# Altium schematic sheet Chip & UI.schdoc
size 478 x 209 mm
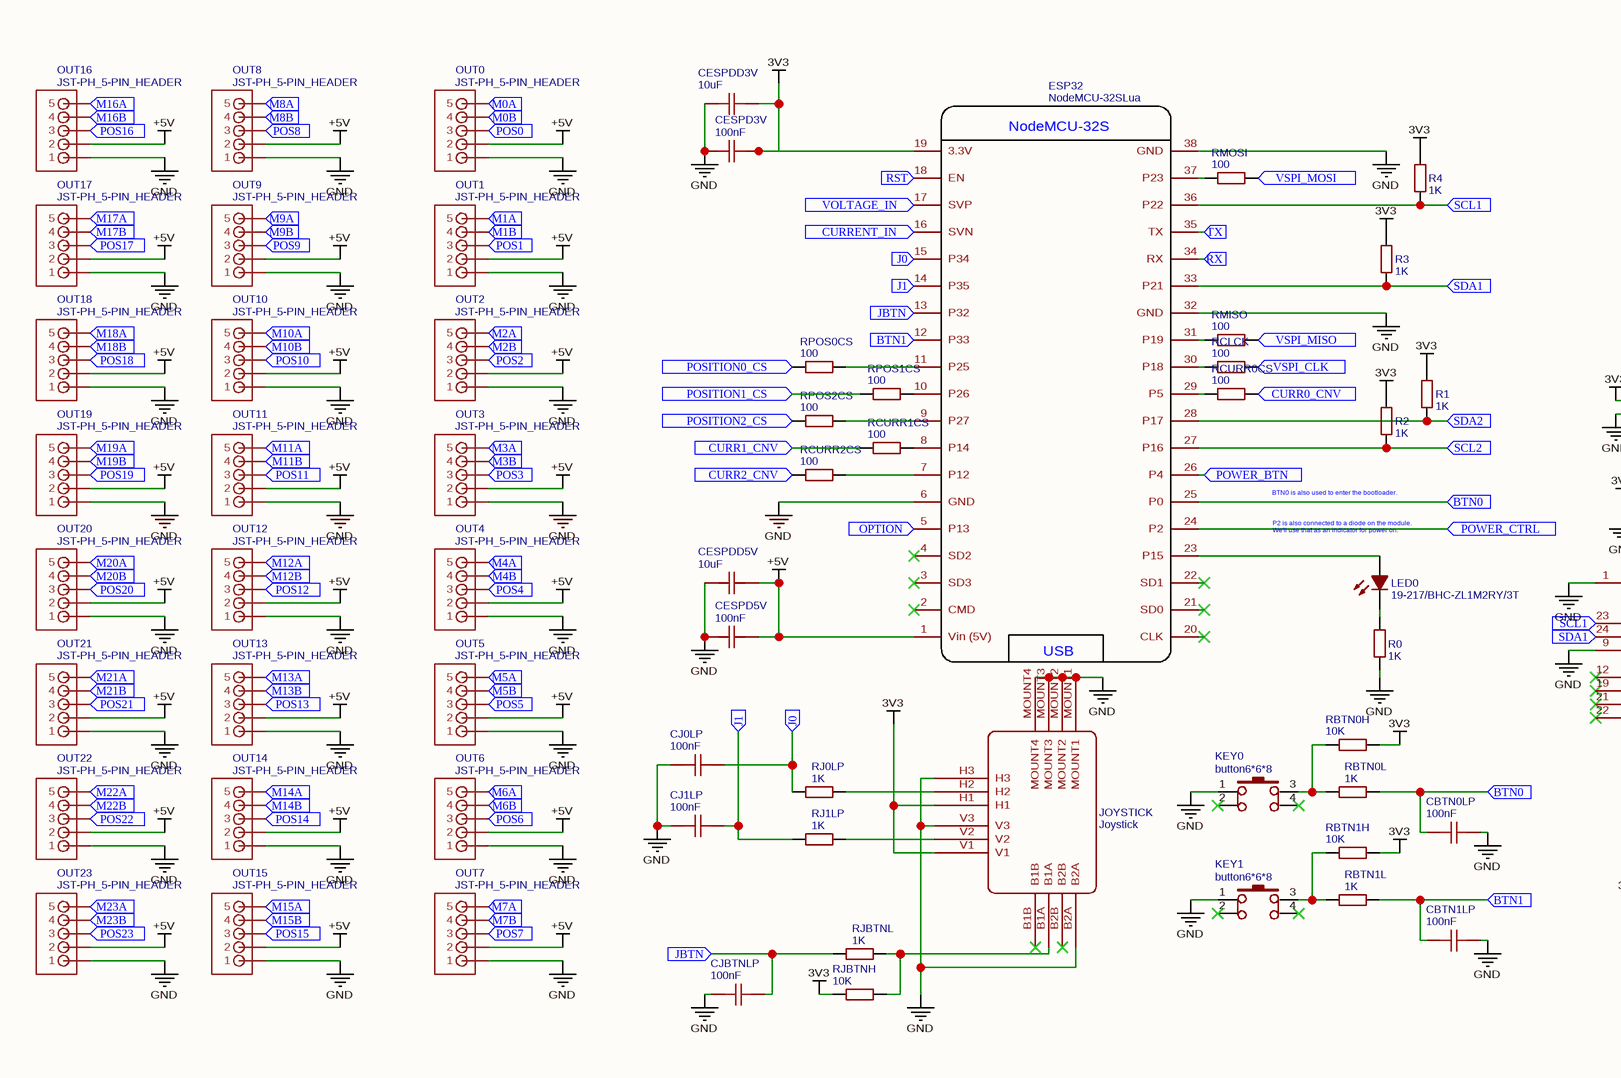
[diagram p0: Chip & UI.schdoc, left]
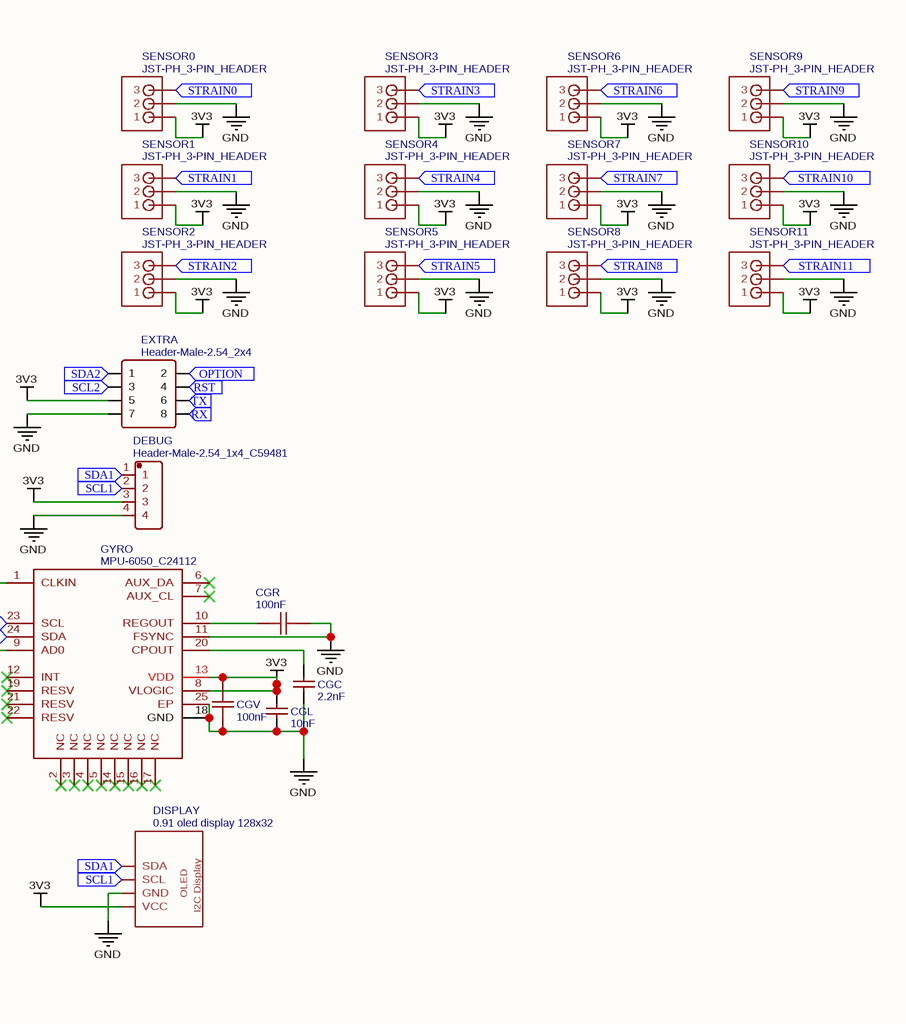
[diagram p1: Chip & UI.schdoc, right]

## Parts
CBTN0LP  100nF  [0603]
CBTN1LP  100nF  [0603]
CESPD3V  100nF  [0603]
CESPD5V  100nF  [0603]
CESPDD3V  10uF  [0603]
CESPDD5V  10uF  [0603]
CGC  2.2nF  [0603]
CGL  10nF  [0603]
CGR  100nF  [0603]
CGV  100nF  [0603]
CJ0LP  100nF  [0603]
CJ1LP  100nF  [0603]
CJBTNLP  100nF  [0603]
DEBUG  Header-Male-2.54_1x4_C59481  [HDR-TH_4P-P2.54-V]
DISPLAY  0.91 oled display 128x32  [OLED_DISPLAY_128X32_0.91]
ESP32  NodeMCU-32SLua  [NODEMCU-32SLUA]
EXTRA  Header-Male-2.54_2x4  [HDR-TH_8P-P2.54-V-R2-C4-S2.54]
GYRO  MPU-6050_C24112  [QFN-24-DOT-BOTTOM-LEFT]
JOYSTICK  Joystick  [JOYSTICK]
KEY0  button6*6*8  [KEY-6.0*6.0-2]
KEY1  button6*6*8  [KEY-6.0*6.0-2]
LED0  19-217/BHC-ZL1M2RY/3T  [LED0603-R-RD]
OUT0  JST-PH_5-PIN_HEADER  [JST_B5B-PH_HEADER]
OUT1  JST-PH_5-PIN_HEADER  [JST_B5B-PH_HEADER]
OUT2  JST-PH_5-PIN_HEADER  [JST_B5B-PH_HEADER]
OUT3  JST-PH_5-PIN_HEADER  [JST_B5B-PH_HEADER]
OUT4  JST-PH_5-PIN_HEADER  [JST_B5B-PH_HEADER]
OUT5  JST-PH_5-PIN_HEADER  [JST_B5B-PH_HEADER]
OUT6  JST-PH_5-PIN_HEADER  [JST_B5B-PH_HEADER]
OUT7  JST-PH_5-PIN_HEADER  [JST_B5B-PH_HEADER]
OUT8  JST-PH_5-PIN_HEADER  [JST_B5B-PH_HEADER]
OUT9  JST-PH_5-PIN_HEADER  [JST_B5B-PH_HEADER]
OUT10  JST-PH_5-PIN_HEADER  [JST_B5B-PH_HEADER]
OUT11  JST-PH_5-PIN_HEADER  [JST_B5B-PH_HEADER]
OUT12  JST-PH_5-PIN_HEADER  [JST_B5B-PH_HEADER]
OUT13  JST-PH_5-PIN_HEADER  [JST_B5B-PH_HEADER]
OUT14  JST-PH_5-PIN_HEADER  [JST_B5B-PH_HEADER]
OUT15  JST-PH_5-PIN_HEADER  [JST_B5B-PH_HEADER]
OUT16  JST-PH_5-PIN_HEADER  [JST_B5B-PH_HEADER]
OUT17  JST-PH_5-PIN_HEADER  [JST_B5B-PH_HEADER]
OUT18  JST-PH_5-PIN_HEADER  [JST_B5B-PH_HEADER]
OUT19  JST-PH_5-PIN_HEADER  [JST_B5B-PH_HEADER]
OUT20  JST-PH_5-PIN_HEADER  [JST_B5B-PH_HEADER]
OUT21  JST-PH_5-PIN_HEADER  [JST_B5B-PH_HEADER]
OUT22  JST-PH_5-PIN_HEADER  [JST_B5B-PH_HEADER]
OUT23  JST-PH_5-PIN_HEADER  [JST_B5B-PH_HEADER]
R0  1K  [0603]
R1  1K  [0603]
R2  1K  [0603]
R3  1K  [0603]
R4  1K  [0603]
RBTN0H  10K  [0603]
RBTN0L  1K  [0603]
RBTN1H  10K  [0603]
RBTN1L  1K  [0603]
RCLCK  100  [0603]
RCURR0CS  100  [0603]
RCURR1CS  100  [0603]
RCURR2CS  100  [0603]
RJ0LP  1K  [0603]
RJ1LP  1K  [0603]
RJBTNH  10K  [0603]
RJBTNL  1K  [0603]
RMISO  100  [0603]
RMOSI  100  [0603]
RPOS0CS  100  [0603]
RPOS1CS  100  [0603]
RPOS2CS  100  [0603]
SENSOR0  JST-PH_3-PIN_HEADER  [JST_B3B-PH_HEADER]
SENSOR1  JST-PH_3-PIN_HEADER  [JST_B3B-PH_HEADER]
SENSOR2  JST-PH_3-PIN_HEADER  [JST_B3B-PH_HEADER]
SENSOR3  JST-PH_3-PIN_HEADER  [JST_B3B-PH_HEADER]
SENSOR4  JST-PH_3-PIN_HEADER  [JST_B3B-PH_HEADER]
SENSOR5  JST-PH_3-PIN_HEADER  [JST_B3B-PH_HEADER]
SENSOR6  JST-PH_3-PIN_HEADER  [JST_B3B-PH_HEADER]
SENSOR7  JST-PH_3-PIN_HEADER  [JST_B3B-PH_HEADER]
SENSOR8  JST-PH_3-PIN_HEADER  [JST_B3B-PH_HEADER]
SENSOR9  JST-PH_3-PIN_HEADER  [JST_B3B-PH_HEADER]
SENSOR10  JST-PH_3-PIN_HEADER  [JST_B3B-PH_HEADER]
SENSOR11  JST-PH_3-PIN_HEADER  [JST_B3B-PH_HEADER]

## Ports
BTN0, BTN1, CURR0_CNV, CURR1_CNV, CURR2_CNV, CURRENT_IN, J0, J1, JBTN, M0A, M0B, M1A, M1B, M2A, M2B, M3A, M3B, M4A, M4B, M5A, M5B, M6A, M6B, M7A, M7B, M8A, M8B, M9A, M9B, M10A, M10B, M11A, M11B, M12A, M12B, M13A, M13B, M14A, M14B, M15A, M15B, M16A, M16B, M17A, M17B, M18A, M18B, M19A, M19B, M20A, M20B, M21A, M21B, M22A, M22B, M23A, M23B, OPTION, POS0, POS1, POS2, POS3, POS4, POS5, POS6, POS7, POS8, POS9, POS10, POS11, POS12, POS13, POS14, POS15, POS16, POS17, POS18, POS19, POS20, POS21, POS22, POS23, POSITION0_CS, POSITION1_CS, POSITION2_CS, POWER_BTN, POWER_CTRL, RST, RX, SCL1, SCL2, SDA1, SDA2, STRAIN0, STRAIN1, STRAIN2, STRAIN3, STRAIN4, STRAIN5, STRAIN6, STRAIN7, STRAIN8, STRAIN9, STRAIN10, STRAIN11, TX, VOLTAGE_IN, VSPI_CLK, VSPI_MISO, VSPI_MOSI

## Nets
3V3: CESPD3V.1 CESPDD3V.1 CGL.2 CGV.2 DEBUG.3 DISPLAY.P$4(VCC) ESP32.19(3.3V) EXTRA.5 GYRO.8(VLOGIC) GYRO.13(VDD) JOYSTICK.H1 JOYSTICK.V1 R1.2 R2.2 R3.2 R4.2 RBTN0H.1 RBTN1H.1 RJBTNH.2 SENSOR0.P1(1) SENSOR1.P1(1) SENSOR2.P1(1) SENSOR3.P1(1) SENSOR4.P1(1) SENSOR5.P1(1) SENSOR6.P1(1) SENSOR7.P1(1) SENSOR8.P1(1) SENSOR9.P1(1) SENSOR10.P1(1) SENSOR11.P1(1)
+5V: CESPD5V.1 CESPDD5V.1 ESP32.1(Vin_(5V)) OUT0.P2(2) OUT1.P2(2) OUT2.P2(2) OUT3.P2(2) OUT4.P2(2) OUT5.P2(2) OUT6.P2(2) OUT7.P2(2) OUT8.P2(2) OUT9.P2(2) OUT10.P2(2) OUT11.P2(2) OUT12.P2(2) OUT13.P2(2) OUT14.P2(2) OUT15.P2(2) OUT16.P2(2) OUT17.P2(2) OUT18.P2(2) OUT19.P2(2) OUT20.P2(2) OUT21.P2(2) OUT22.P2(2) OUT23.P2(2)
GND: CBTN0LP.2 CBTN1LP.2 CESPD3V.2 CESPD5V.2 CESPDD3V.2 CESPDD5V.2 CGC.1 CGL.1 CGR.2 CGV.1 CJ0LP.1 CJ1LP.1 CJBTNLP.1 DEBUG.4 DISPLAY.P$3(GND) ESP32.6(GND) ESP32.32(GND) ESP32.38(GND) EXTRA.7 GYRO.1(CLKIN) GYRO.9(AD0) GYRO.11(FSYNC) GYRO.18(GND) GYRO.25(EP) JOYSTICK.B2A JOYSTICK.H3 JOYSTICK.MOUNT1 JOYSTICK.MOUNT2 JOYSTICK.MOUNT3 JOYSTICK.MOUNT4 JOYSTICK.V3 KEY0.1 KEY1.1 OUT0.P1(1) OUT1.P1(1) OUT2.P1(1) OUT3.P1(1) OUT4.P1(1) OUT5.P1(1) OUT6.P1(1) OUT7.P1(1) OUT8.P1(1) OUT9.P1(1) OUT10.P1(1) OUT11.P1(1) OUT12.P1(1) OUT13.P1(1) OUT14.P1(1) OUT15.P1(1) OUT16.P1(1) OUT17.P1(1) OUT18.P1(1) OUT19.P1(1) OUT20.P1(1) OUT21.P1(1) OUT22.P1(1) OUT23.P1(1) R0.1 SENSOR0.P2(2) SENSOR1.P2(2) SENSOR2.P2(2) SENSOR3.P2(2) SENSOR4.P2(2) SENSOR5.P2(2) SENSOR6.P2(2) SENSOR7.P2(2) SENSOR8.P2(2) SENSOR9.P2(2) SENSOR10.P2(2) SENSOR11.P2(2)
BTN0: CBTN0LP.1 ESP32.25(P0) RBTN0L.1 ; port BTN0
BTN1: CBTN1LP.1 ESP32.12(P33) RBTN1L.1 ; port BTN1
CURR0_CNV: RCURR0CS.1 ; port CURR0_CNV
CURR1_CNV: RCURR1CS.2 ; port CURR1_CNV
CURR2_CNV: RCURR2CS.2 ; port CURR2_CNV
CURRENT_IN: ESP32.16(SVN) ; port CURRENT_IN
J0: CJ0LP.2 ESP32.15(P34) RJ0LP.2 ; port J0
J1: CJ1LP.2 ESP32.14(P35) RJ1LP.2 ; port J1
JBTN: CJBTNLP.2 ESP32.13(P32) RJBTNL.2 ; port JBTN
M0A: OUT0.P5(5) ; port M0A
M0B: OUT0.P4(4) ; port M0B
M1A: OUT1.P5(5) ; port M1A
M1B: OUT1.P4(4) ; port M1B
M2A: OUT2.P5(5) ; port M2A
M2B: OUT2.P4(4) ; port M2B
M3A: OUT3.P5(5) ; port M3A
M3B: OUT3.P4(4) ; port M3B
M4A: OUT4.P5(5) ; port M4A
M4B: OUT4.P4(4) ; port M4B
M5A: OUT5.P5(5) ; port M5A
M5B: OUT5.P4(4) ; port M5B
M6A: OUT6.P5(5) ; port M6A
M6B: OUT6.P4(4) ; port M6B
M7A: OUT7.P5(5) ; port M7A
M7B: OUT7.P4(4) ; port M7B
M8A: OUT8.P5(5) ; port M8A
M8B: OUT8.P4(4) ; port M8B
M9A: OUT9.P5(5) ; port M9A
M9B: OUT9.P4(4) ; port M9B
M10A: OUT10.P5(5) ; port M10A
M10B: OUT10.P4(4) ; port M10B
M11A: OUT11.P5(5) ; port M11A
M11B: OUT11.P4(4) ; port M11B
M12A: OUT12.P5(5) ; port M12A
M12B: OUT12.P4(4) ; port M12B
M13A: OUT13.P5(5) ; port M13A
M13B: OUT13.P4(4) ; port M13B
M14A: OUT14.P5(5) ; port M14A
M14B: OUT14.P4(4) ; port M14B
M15A: OUT15.P5(5) ; port M15A
M15B: OUT15.P4(4) ; port M15B
M16A: OUT16.P5(5) ; port M16A
M16B: OUT16.P4(4) ; port M16B
M17A: OUT17.P5(5) ; port M17A
M17B: OUT17.P4(4) ; port M17B
M18A: OUT18.P5(5) ; port M18A
M18B: OUT18.P4(4) ; port M18B
M19A: OUT19.P5(5) ; port M19A
M19B: OUT19.P4(4) ; port M19B
M20A: OUT20.P5(5) ; port M20A
M20B: OUT20.P4(4) ; port M20B
M21A: OUT21.P5(5) ; port M21A
M21B: OUT21.P4(4) ; port M21B
M22A: OUT22.P5(5) ; port M22A
M22B: OUT22.P4(4) ; port M22B
M23A: OUT23.P5(5) ; port M23A
M23B: OUT23.P4(4) ; port M23B
OPTION: ESP32.5(P13) EXTRA.2 ; port OPTION
POS0: OUT0.P3(3) ; port POS0
POS1: OUT1.P3(3) ; port POS1
POS2: OUT2.P3(3) ; port POS2
POS3: OUT3.P3(3) ; port POS3
POS4: OUT4.P3(3) ; port POS4
POS5: OUT5.P3(3) ; port POS5
POS6: OUT6.P3(3) ; port POS6
POS7: OUT7.P3(3) ; port POS7
POS8: OUT8.P3(3) ; port POS8
POS9: OUT9.P3(3) ; port POS9
POS10: OUT10.P3(3) ; port POS10
POS11: OUT11.P3(3) ; port POS11
POS12: OUT12.P3(3) ; port POS12
POS13: OUT13.P3(3) ; port POS13
POS14: OUT14.P3(3) ; port POS14
POS15: OUT15.P3(3) ; port POS15
POS16: OUT16.P3(3) ; port POS16
POS17: OUT17.P3(3) ; port POS17
POS18: OUT18.P3(3) ; port POS18
POS19: OUT19.P3(3) ; port POS19
POS20: OUT20.P3(3) ; port POS20
POS21: OUT21.P3(3) ; port POS21
POS22: OUT22.P3(3) ; port POS22
POS23: OUT23.P3(3) ; port POS23
POSITION0_CS: RPOS0CS.2 ; port POSITION0_CS
POSITION1_CS: RPOS1CS.2 ; port POSITION1_CS
POSITION2_CS: RPOS2CS.2 ; port POSITION2_CS
POWER_BTN: ESP32.26(P4) ; port POWER_BTN
POWER_CTRL: ESP32.24(P2) ; port POWER_CTRL
RST: ESP32.18(EN) EXTRA.4 ; port RST
RX: ESP32.34(RX) EXTRA.8 ; port RX
SCL1: DEBUG.2 DISPLAY.P$2(SCL) ESP32.36(P22) GYRO.23(SCL) R4.1 ; port SCL1
SCL2: ESP32.27(P16) EXTRA.3 R2.1 ; port SCL2
SDA1: DEBUG.1 DISPLAY.P$1(SDA) ESP32.33(P21) GYRO.24(SDA) R3.1 ; port SDA1
SDA2: ESP32.28(P17) EXTRA.1 R1.1 ; port SDA2
STRAIN0: SENSOR0.P3(3) ; port STRAIN0
STRAIN1: SENSOR1.P3(3) ; port STRAIN1
STRAIN2: SENSOR2.P3(3) ; port STRAIN2
STRAIN3: SENSOR3.P3(3) ; port STRAIN3
STRAIN4: SENSOR4.P3(3) ; port STRAIN4
STRAIN5: SENSOR5.P3(3) ; port STRAIN5
STRAIN6: SENSOR6.P3(3) ; port STRAIN6
STRAIN7: SENSOR7.P3(3) ; port STRAIN7
STRAIN8: SENSOR8.P3(3) ; port STRAIN8
STRAIN9: SENSOR9.P3(3) ; port STRAIN9
STRAIN10: SENSOR10.P3(3) ; port STRAIN10
STRAIN11: SENSOR11.P3(3) ; port STRAIN11
TX: ESP32.35(TX) EXTRA.6 ; port TX
VOLTAGE_IN: ESP32.17(SVP) ; port VOLTAGE_IN
VSPI_CLK: RCLCK.1 ; port VSPI_CLK
VSPI_MISO: RMISO.1 ; port VSPI_MISO
VSPI_MOSI: RMOSI.1 ; port VSPI_MOSI
NetCGC_2: CGC.2 GYRO.20(CPOUT)
NetCGR_1: CGR.1 GYRO.10(REGOUT)
NetESP32_7: ESP32.7(P12) RCURR2CS.1
NetESP32_8: ESP32.8(P14) RCURR1CS.1
NetESP32_9: ESP32.9(P27) RPOS2CS.1
NetESP32_10: ESP32.10(P26) RPOS1CS.1
NetESP32_11: ESP32.11(P25) RPOS0CS.1
NetESP32_23: ESP32.23(P15) LED0.1(A)
NetESP32_29: ESP32.29(P5) RCURR0CS.2
NetESP32_30: ESP32.30(P18) RCLCK.2
NetESP32_31: ESP32.31(P19) RMISO.2
NetESP32_37: ESP32.37(P23) RMOSI.2
NetJOYSTICK_B1A: JOYSTICK.B1A RJBTNH.1 RJBTNL.1
NetJOYSTICK_H2: JOYSTICK.H2 RJ0LP.1
NetJOYSTICK_V2: JOYSTICK.V2 RJ1LP.1
NetKEY0_3: KEY0.3 RBTN0H.2 RBTN0L.2
NetKEY1_3: KEY1.3 RBTN1H.2 RBTN1L.2
NetLED0_2: LED0.2(C) R0.2

Not connected (* = marked no-connect by the designer): ESP32 2(CMD)* 3(SD3)* 4(SD2)* 20(CLK)* 21(SD0)* 22(SD1)*; GYRO 2(NC)* 3(NC)* 4(NC)* 5(NC)* 6(AUX_DA)* 7(AUX_CL)* 12(INT)* 14(NC)* 15(NC)* 16(NC)* 17(NC)* 19(RESV)* 21(RESV)* 22(RESV)*; JOYSTICK B1B* B2B*; KEY0 2* 4*; KEY1 2* 4*

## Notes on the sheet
- BTN0 is also used to enter the bootloader.
- P2 is also connected to a diode on the module.
  We'll use that as an indicator for power on.

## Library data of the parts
CBTN0LP CBTN1LP CESPD3V CESPD5V CGR CGV CJ0LP CJ1LP CJBTNLP = 100nF: BOM_Manufacturer: YAGEO; BOM_Manufacturer Part: CC0603KRX7R9BB104; nameAlias: Capacitance; SMT Type: Basic
CESPDD3V CESPDD5V = 10uF: BOM_Manufacturer: SAMSUNG; BOM_Manufacturer Part: CL10A106KP8NNNC; nameAlias: Capacitance; SMT Type: Basic
CGC = 2.2nF: BOM_Manufacturer: FH; BOM_Manufacturer Part: 0603B222K500NT; nameAlias: Capacitance; SMT Type: Basic
CGL = 10nF: BOM_Manufacturer: FH; BOM_Manufacturer Part: 0603B103K500NT; nameAlias: Capacitance; SMT Type: Basic
DEBUG = Header-Male-2.54_1x4_C59481: BOM_Manufacturer: ReliaPro; BOM_Manufacturer Part: Headers??Pins 1*4P
DISPLAY = 0.91 oled display 128x32: Contributor: Angius
ESP32 = NodeMCU-32SLua: BOM_Manufacturer: Ai-Thinker; Contributor: EasyEDA
EXTRA = Header-Male-2.54_2x4: BOM_Manufacturer: ReliaPro; BOM_Manufacturer Part: Header2X4P 2.54mm
GYRO = MPU-6050_C24112: BOM_Manufacturer: InvenSense; sourceId: 1T5FDZYC8; SMT Type: Basic
JOYSTICK = Joystick: sourceId: 1T5FDZYC8
KEY0 KEY1 = button6*6*8: BOM_Manufacturer: ReliaPro
LED0 = 19-217/BHC-ZL1M2RY/3T: BOM_Manufacturer: EVERLIGHT; SMT Type: Basic
R0-R4 RBTN0L RBTN1L RJ0LP RJ1LP RJBTNL = 1K: BOM_Manufacturer: UniOhm; BOM_Manufacturer Part: 0603WAF1001T5E; nameAlias: Resistance (Ohms); SMT Type: Basic
RBTN0H RBTN1H RJBTNH = 10K: BOM_Manufacturer: UniOhm; BOM_Manufacturer Part: 0603WAF1002T5E; nameAlias: Resistance (Ohms); SMT Type: Basic
RCLCK RCURR0CS RCURR1CS RCURR2CS RMISO RMOSI RPOS0CS RPOS1CS RPOS2CS = 100: BOM_Manufacturer: UniOhm; BOM_Manufacturer Part: 0603WAF1000T5E; nameAlias: Resistance (Ohms); SMT Type: Basic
